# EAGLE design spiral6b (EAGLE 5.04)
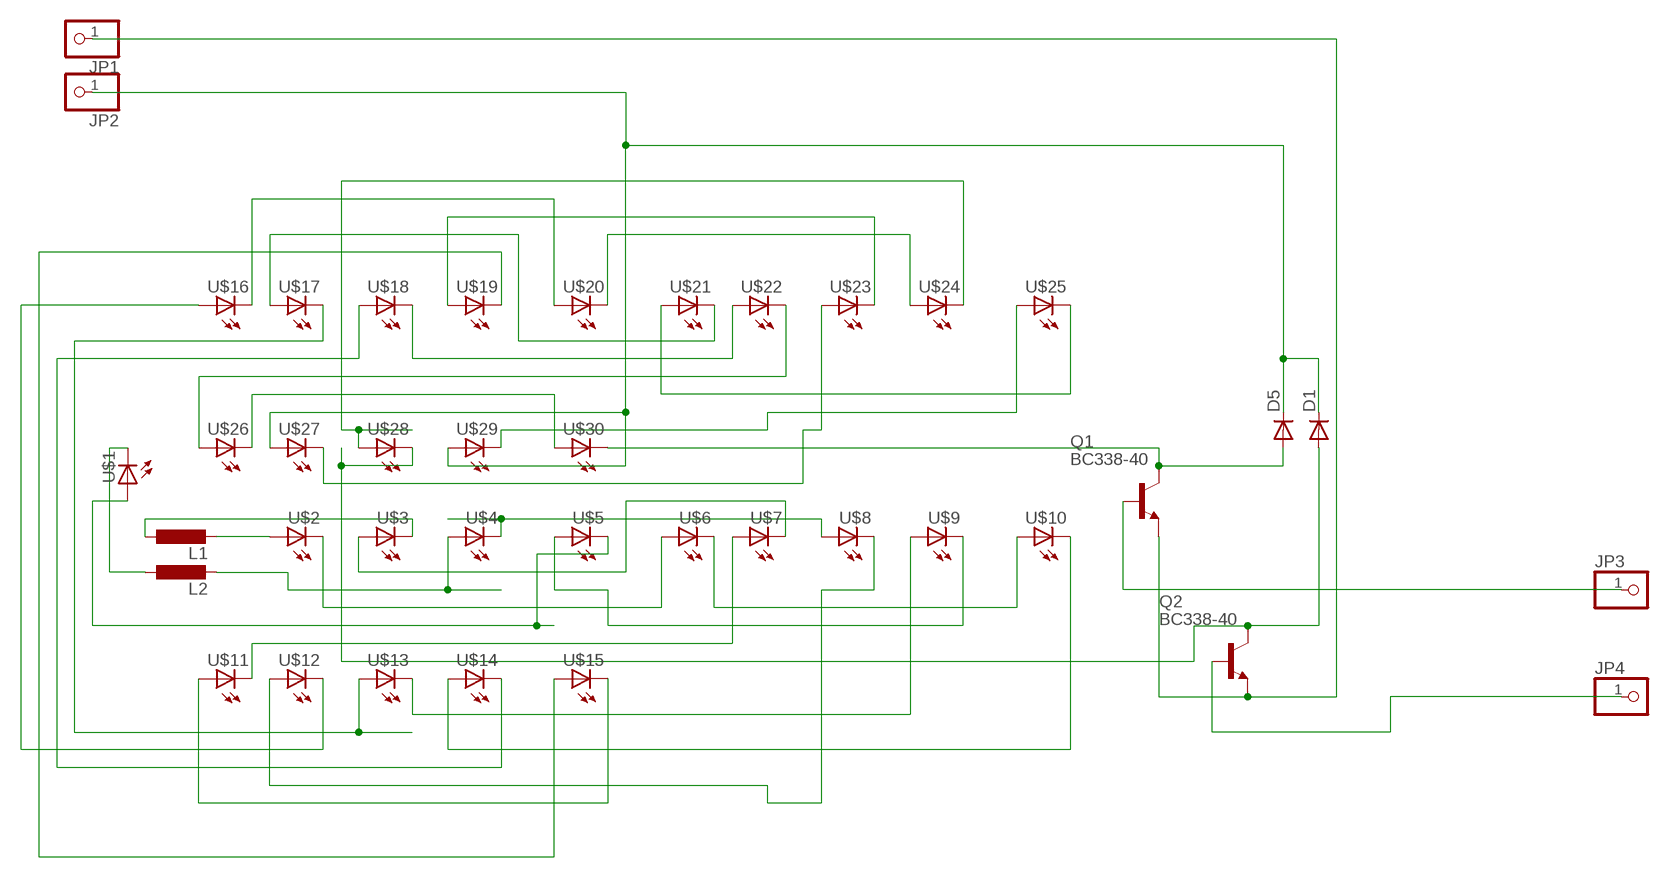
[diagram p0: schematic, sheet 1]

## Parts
D1  DIODE-D-2.5  [D-2.5]
D5  DIODE-D-2.5  [D-2.5]
JP1  PINHD-1X1  [1X01]
JP2  PINHD-1X1  [1X01]
JP3  PINHD-1X1  [1X01]
JP4  PINHD-1X1  [1X01]
L1  L-EU0207/10  [0207/10]
L2  L-EU0207/10  [0207/10]
Q1  BC338-40  [TO92-EBC]
Q2  BC338-40  [TO92-EBC]
U$1  LED5MM  [LED5MM]
U$2  LED5MM  [LED5MM]
U$3  LED5MM  [LED5MM]
U$4  LED5MM  [LED5MM]
U$5  LED5MM  [LED5MM]
U$6  LED5MM  [LED5MM]
U$7  LED5MM  [LED5MM]
U$8  LED5MM  [LED5MM]
U$9  LED5MM  [LED5MM]
U$10  LED5MM  [LED5MM]
U$11  LED5MM  [LED5MM]
U$12  LED5MM  [LED5MM]
U$13  LED5MM  [LED5MM]
U$14  LED5MM  [LED5MM]
U$15  LED5MM  [LED5MM]
U$16  LED5MM  [LED5MM]
U$17  LED5MM  [LED5MM]
U$18  LED5MM  [LED5MM]
U$19  LED5MM  [LED5MM]
U$20  LED5MM  [LED5MM]
U$21  LED5MM  [LED5MM]
U$22  LED5MM  [LED5MM]
U$23  LED5MM  [LED5MM]
U$24  LED5MM  [LED5MM]
U$25  LED5MM  [LED5MM]
U$26  LED5MM  [LED5MM]
U$27  LED5MM  [LED5MM]
U$28  LED5MM  [LED5MM]
U$29  LED5MM  [LED5MM]
U$30  LED5MM  [LED5MM]

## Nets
N$1: JP1.1 Q1.E Q2.E
N$2: U$2.K(C) U$6.A
N$3: L1.2 U$2.A
N$4: U$6.K(C) U$10.A
N$5: L1.1 U$3.K(C)
N$6: L2.1 U$1.K(C)
N$7: U$3.A U$7.K(C)
N$8: U$19.A U$23.K(C)
N$9: U$9.A U$13.K(C)
N$10: U$10.K(C) U$14.A
N$11: U$25.A U$29.K(C)
N$12: U$14.K(C) U$18.A
N$13: U$16.K(C) U$20.A
N$14: L2.2 U$4.A
N$15: U$18.K(C) U$22.A
N$16: U$5.A U$9.K(C)
N$17: U$22.K(C) U$26.A
N$18: U$26.K(C) U$30.A
N$19: U$4.K(C) U$8.A
N$20: JP4.1 Q2.B
N$21: U$8.K(C) U$12.A
N$22: U$1.A U$5.K(C)
N$24: U$23.A U$27.K(C)
N$25: U$12.K(C) U$16.A
N$26: D1.A Q2.C U$28.K(C)
N$27: U$7.A U$11.K(C)
N$28: U$20.K(C) U$24.A
N$29: U$11.A U$15.K(C)
N$30: U$24.K(C) U$28.A
N$31: U$15.A U$19.K(C)
N$32: U$13.A U$17.K(C)
N$33: U$17.A U$21.K(C)
N$35: U$21.A U$25.K(C)
N$36: D5.A Q1.C U$30.K(C)
N$40: JP3.1 Q1.B
V300: D1.C D5.C JP2.1 U$27.A U$29.A

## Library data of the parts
D1 D5 = diode-1:DIODE-: DIODE
JP1-JP4 = pinhead:PINHD-1X1: PIN HEADER
L1 L2 = rcl-2:L-EU: INDUCTOR, European symbol
Q1 Q2 = transistor-npn:BC338*: NPN Transistor
U$1-U$30 = led(2):LED: LED

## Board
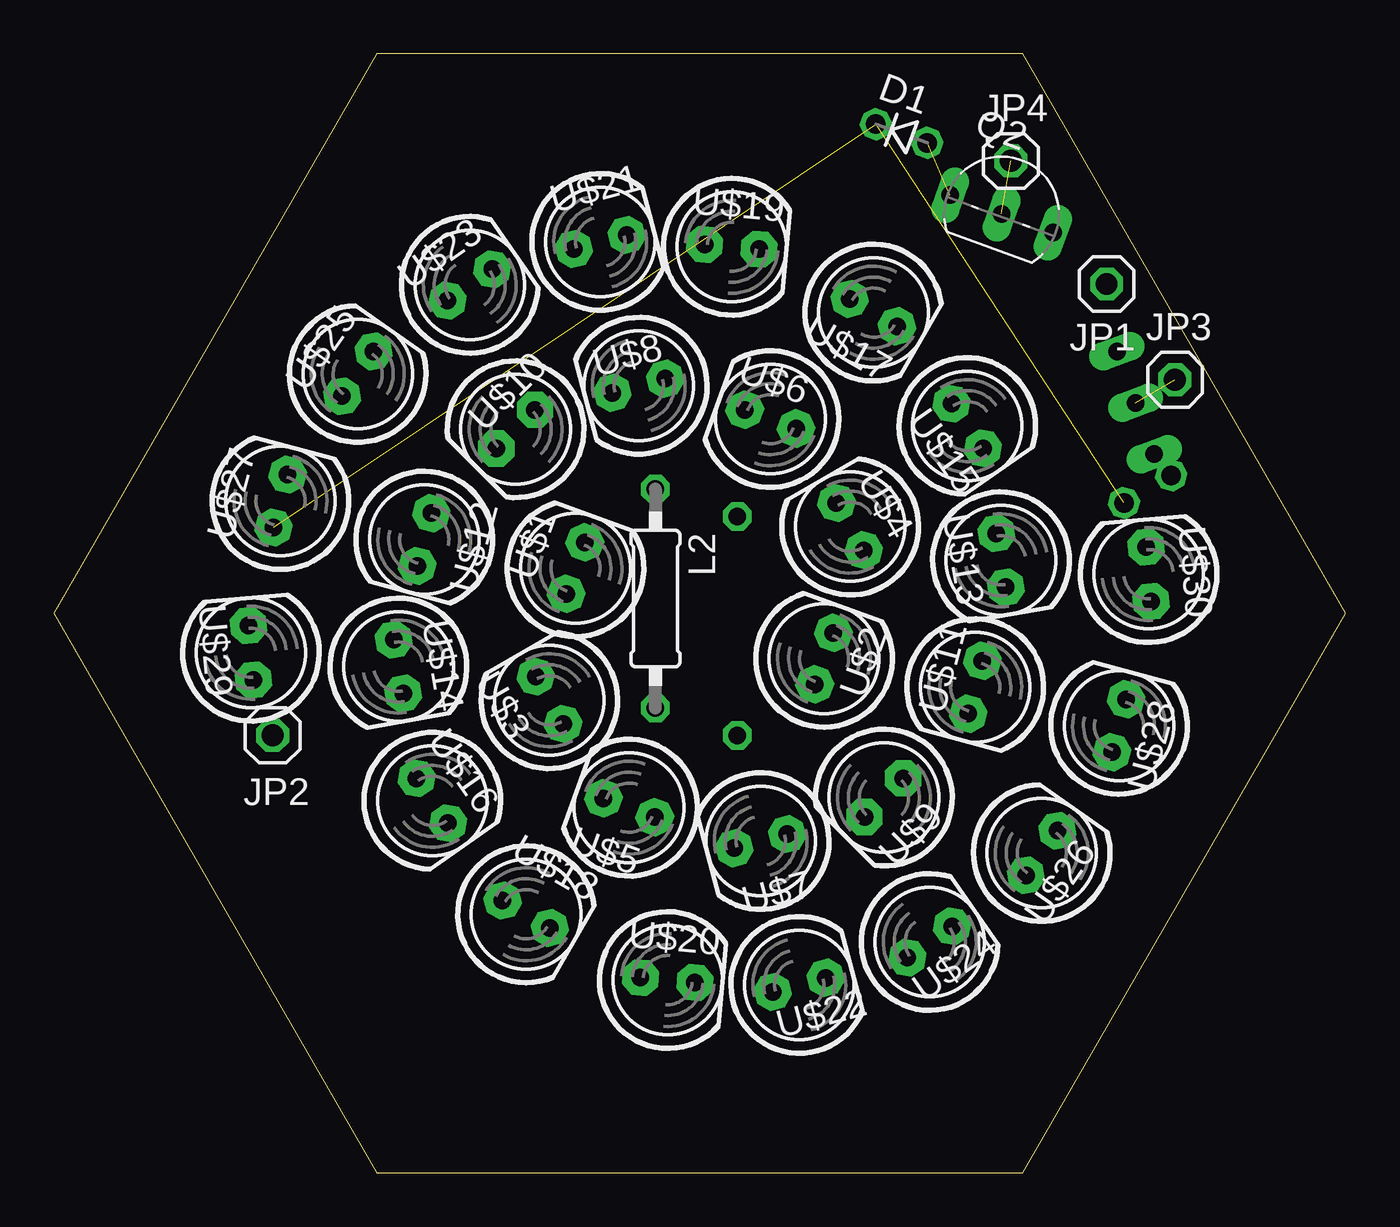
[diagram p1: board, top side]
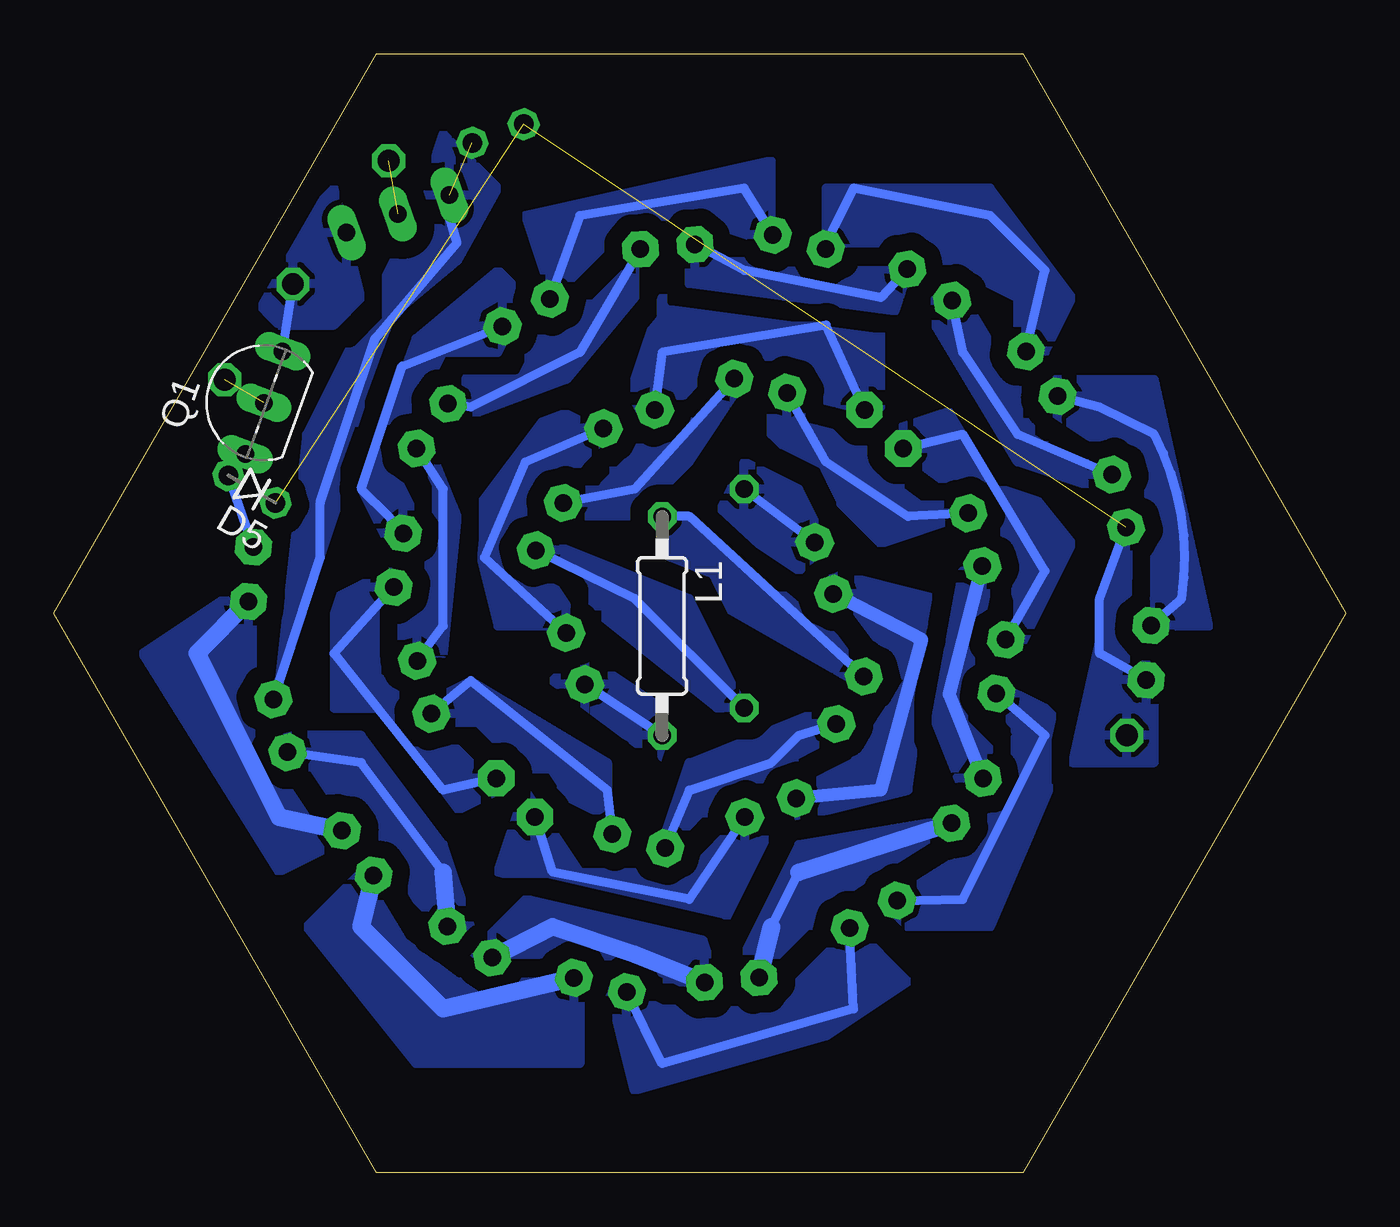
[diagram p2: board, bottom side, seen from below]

Size 60 x 51.96 mm. Coordinates in mm from the lower left corner, seen from the top.
Outline: 15,0 45,0 60,25.98 45,51.96 15,51.96 0,25.98 15,0
Copper layers (1*16): Top 0.035mm / dielectric 1.5mm / Bottom 0.035mm
Design rules "default": minimum track width 10mil, minimum drill 24mil, track to track 8mil, track to pad 8mil, pad to pad 8mil, via to via 8mil, smd to smd 8mil, copper to edge 40mil, drill to drill 8mil, minimum pad ring 10mil, minimum via ring 8mil, stop-mask expansion 4mil, vias tented up to drill 0mil, thermal gap 10mil

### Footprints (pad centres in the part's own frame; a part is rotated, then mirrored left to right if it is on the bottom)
D-2.5 = drill 0.9 octagon: A 1.27,0; C -1.27,0
1X01 = drill 1.016 octagon: 1 0,0
0207/10 = drill 0.813 octagon: 1 -5.08,0; 2 5.08,0
TO92-EBC = drill 0.813 long: B 0,-1.27; C -2.54,-1.27; E 2.54,-1.27
LED5MM = drill 0.813 pad 1.676 octagon: A -1.27,0; K 1.27,0

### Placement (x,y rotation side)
D1  39.37,48.26 340 top
D5  50.8,31.75 150 bottom
JP1  48.9,41.27 180 top
JP2  10.16,20.32 0 top
JP3  52.07,36.83 0 top
JP4  44.45,46.99 0 top
L1  31.75,25.4 270 bottom
L2  27.94,26.67 270 top
Q1  51.44,36.2 70 bottom
Q2  44.45,45.72 340 top
U$1  24.23,28.08 70 top
U$2  35.77,23.88 70 top
U$3  23.02,21.95 120 top
U$4  36.98,30.01 120 top
U$5  26.72,16.96 160 top
U$6  33.28,35 160 top
U$7  32.83,15.41 195 top
U$8  27.17,36.55 195 top
U$9  38.55,17.43 225 top
U$10  21.45,34.53 225 top
U$11  42.8,22.55 255 top
U$12  17.2,29.41 255 top
U$13  43.99,28.45 280 top
U$14  16.01,23.51 280 top
U$15  42.42,34.68 305 top
U$16  17.58,17.28 305 top
U$17  38.06,39.95 330 top
U$18  21.94,12.01 330 top
U$19  31.49,43 355 top
U$20  28.51,8.96 355 top
U$21  25.38,43.23 14.9 top
U$22  34.62,8.73 14.9 top
U$23  19.32,41.23 35 top
U$24  40.68,10.73 35 top
U$25  14.12,37.1 54.9 top
U$26  45.88,14.86 54.9 top
U$27  10.53,31.2 75 top
U$28  49.47,20.76 75 top
U$29  9.15,24.16 95 top
U$30  50.85,27.8 95 top

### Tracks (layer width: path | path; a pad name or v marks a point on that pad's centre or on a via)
N$1
  Bottom 0.406: Q1.E JP1.1
  pour Bottom: 46.99,45.72 50.8,41.91 50.8,40.64 49.53,39.37 46.99,39.37 45.72,40.64
N$2
  Bottom 0.406: U$6.A 38.1,33.02 40.01,28.57 U$2.K
  pour Bottom (isolate 0.813, rank 3): 34.29,34.29 36.83,35.56 40.64,30.48 39.37,25.4 35.56,25.4 38.1,29.21 35.56,33.02
N$3
  Bottom 0.406: L1.2 U$2.A
  pour Bottom (isolate 0.813, rank 5): 31.75,21.59 35.56,24.13 36.83,22.86 31.75,19.05
N$4
  Bottom 0.406: U$10.A 24.13,39.37 31.75,38.1 U$6.K
  pour Bottom (isolate 0.813, rank 3): 21.59,35.56 21.59,39.37 31.75,40.64 33.02,36.83 33.02,35.56 27.94,36.83 22.86,35.56
N$5
  Bottom 0.406: U$3.K 30.48,30.48 L1.1
  pour Bottom (isolate 0.813, rank 5): 22.86,22.86 31.75,27.94 31.75,30.48 30.48,30.48 22.86,24.13
N$6
  Bottom 0.406: U$1.K L2.1
  pour Bottom (isolate 0.813, rank 3): 24.13,29.21 25.4,31.75 27.94,33.02 29.21,30.48 25.4,27.94
N$7
  Bottom 0.406: U$3.A 25.4,20.32 26.67,19.05 30.48,17.78 U$7.K
  pour Bottom (isolate 0.813, rank 4): 31.75,15.24 30.48,19.05 24.13,21.59 22.86,20.32 29.21,16.51
N$8
  Bottom 0.406: U$23.K 21.59,40.64 27.94,41.91 U$19.A
  pour Bottom (isolate 0.813, rank 2): 20.32,41.91 20.95,40.01 30.48,41.27 30.48,43.18 23.5,41.91
N$9
  Bottom 0.406: U$13.K 46.99,24.13 41.91,17.78 U$9.A
  pour Bottom (isolate 0.813, rank 3): 44.45,27.94 46.99,26.67 46.99,21.59 41.91,16.51 39.37,17.78 41.91,20.32 44.45,22.86 44.45,24.13
N$10
  Bottom 0.406: U$14.A 13.97,27.94 17.78,34.29 U$10.K
  pour Bottom (isolate 0.813, rank 3): 15.24,24.13 12.7,29.21 17.78,35.56 21.59,34.29 16.51,30.48 15.24,26.67
N$11
  Bottom 0.406: U$29.K 7.62,26.67 arc-37 8.89,34.29 11.43,35.56 U$25.A
  pour Bottom (isolate 0.813): 8.89,25.4 6.35,25.4 8.89,36.83 13.97,36.83 13.97,35.56 10.16,33.02 8.89,29.21 8.89,26.67
N$12
  Bottom 0.406: U$18.A 17.78,12.7 13.97,20.32 U$14.K
  pour Bottom (isolate 0.813, rank 3): 16.51,22.86 13.97,21.59 12.7,20.32 16.51,11.43 20.32,11.43 21.59,12.7 15.24,20.32
N$13
  Bottom 0.406: 26.67,11.43 25.4,13.97
  Bottom 0.813: 25.4,13.97 U$16.K | U$20.A 26.67,11.43
  pour Bottom (isolate 0.813, rank 2): 17.78,16.51 25.4,15.24 27.94,10.16 27.3,8.89 23.5,12.7 22.86,13.34
N$14
  Bottom 0.406: L2.2 33.02,26.67 U$4.A
  pour Bottom (isolate 0.813, rank 4): 27.94,21.59 30.48,26.67 36.83,29.21 35.56,26.67 29.21,21.59
N$15
  Bottom 0.406: U$22.A 31.75,5.08 22.86,7.62 U$18.K
  pour Bottom (isolate 0.813): 22.86,11.43 20.32,8.89 24.13,6.35 33.02,3.81 34.29,8.89 31.75,7.62 26.67,7.62
N$16
  Bottom 0.406: U$9.K 36.83,13.97 30.48,12.7 U$5.A
  pour Bottom (isolate 0.813, rank 3): 27.94,16.51 26.67,15.24 29.21,10.16 39.37,13.97 38.1,17.78 35.56,13.97 30.48,13.97
N$17
  Bottom 0.813: U$26.A 45.72,11.43 41.91,7.62 U$22.K
  pour Bottom (isolate 0.813): 35.56,8.89 35.56,5.08 43.18,5.08 48.26,11.43 45.72,13.97 43.81,10.79 41.27,8.89
N$18
  Bottom 0.813: U$30.A 53.34,24.13 49.53,16.51 U$26.K
  pour Bottom (isolate 0.813): 46.99,15.24 49.53,13.97 55.88,24.13 52.07,26.67 50.8,25.4 50.8,20.32 48.26,16.51
N$19
  Bottom 0.406: U$4.K 33.02,31.75 U$8.A
  pour Bottom (isolate 0.813, rank 4): 27.94,36.83 30.48,33.02 33.02,30.48 36.83,30.48 35.56,31.75 29.21,36.83
N$20  (1 unrouted)
N$21
  Bottom 0.406: U$8.K 24.13,33.02 20.32,30.48 U$12.A
  pour Bottom (isolate 0.813, rank 4): 17.78,30.48 21.59,29.21 26.67,34.29 26.67,35.56 25.4,36.83 21.59,33.02
N$22
  Bottom 0.61: U$5.K 21.59,17.78 19.68,24.77 U$1.A
  pour Bottom (isolate 0.813, rank 3): 25.4,16.51 20.32,17.78 19.05,26.67 24.13,27.94 20.32,22.86 22.86,19.05 25.4,17.78
N$24
  Bottom 0.406: U$27.K 15.24,34.29 17.78,38.1 U$23.A
  pour Bottom (isolate 0.813, rank 2): 11.43,31.75 15.24,33.02 19.05,39.37 19.05,40.64 17.78,40.64 13.97,34.29 11.43,33.02
N$25
  Bottom 0.61: U$12.K 18.41,22.23 U$16.A
  pour Bottom (isolate 0.813, rank 2): 17.78,17.78 19.05,20.95 17.78,27.94 16.51,27.94 17.14,24.77 17.78,20.95 16.51,19.68
N$26  (1 unrouted)
  Bottom 0.406: U$28.K 47.62,28.57 47.62,31.11 45.09,38.73 41.27,43.18 41.91,45.4 Q2.C
  pour Bottom (isolate 0.813, rank 2): 49.53,22.86 45.72,34.29 39.37,45.72 41.91,48.26 43.18,44.45 48.26,34.29
N$27
  Bottom 0.406: U$7.A 34.29,17.78 40.64,22.86 U$11.K
  pour Bottom (isolate 0.813, rank 4): 43.18,21.59 40.64,22.86 34.29,19.05 34.29,16.51 36.83,17.78 40.64,20.32
N$28
  Bottom 0.813: U$20.K 33.02,10.16 36.83,11.43 U$24.A
  pour Bottom (isolate 0.813, rank 2): 29.21,8.89 29.84,10.79 38.1,12.7 40.64,10.16 35.56,10.16 31.75,8.89
N$29
  Bottom 0.406: U$15.K 41.91,31.75 41.91,25.4 U$11.A
  pour Bottom (isolate 0.813, rank 2): 42.55,33.66 41.27,30.48 41.91,24.13 43.81,24.13 43.81,31.75
N$30
  Bottom 0.406: 41.91,13.97 45.72,19.05 U$28.A
  Bottom 0.813: U$24.K 41.91,13.97
  pour Bottom (isolate 0.813, rank 2): 40.64,11.43 41.91,15.24 45.72,20.32 49.53,20.32 45.72,15.24 41.91,11.43
N$31
  Bottom 0.406: U$19.K 35.56,38.1 40.64,35.56 U$15.A
  pour Bottom (isolate 0.813, rank 2): 33.02,43.18 33.02,40.64 36.2,36.83 41.27,34.92 42.55,36.2 33.66,42.55
N$32
  Bottom 0.406: U$17.K 43.81,37.47 45.72,31.75 44.45,30.48 U$13.A
  pour Bottom (isolate 0.813): 38.1,40.64 39.37,41.91 43.18,38.73 45.72,31.75 44.45,29.21 43.18,30.48 44.45,33.02 41.91,38.1 39.37,38.1
N$33
  Bottom 0.406: U$21.K 27.94,45.72 35.56,44.45 U$17.A
  pour Bottom (isolate 0.813): 26.67,43.18 26.67,46.99 38.1,44.45 36.83,40.64 34.29,43.18 30.48,44.45
N$35
  Bottom 0.406: U$25.K 13.97,41.91 16.51,44.45 22.86,45.72 24.13,43.18 U$21.A
  pour Bottom (isolate 0.813): 13.97,38.1 12.7,40.64 16.51,45.72 24.13,45.72 24.13,43.18 20.32,43.18 15.24,40.64 15.24,39.37
N$36
  Bottom 0.406: Q1.C D5.A U$30.K
N$40  (1 unrouted)
V300  (2 unrouted)
  Bottom 0.406: U$27.A 11.43,26.67 11.43,24.13 U$29.A
  pour Bottom (isolate 0.813, rank 2): 8.89,22.86 10.16,30.48 12.7,19.05 8.89,19.05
